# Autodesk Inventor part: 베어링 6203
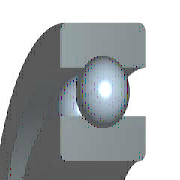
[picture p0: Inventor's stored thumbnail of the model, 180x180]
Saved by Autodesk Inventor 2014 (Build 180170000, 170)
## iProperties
IsCustomPart: 0
Company: 한국ATC센터
Created: 2014-10
Part Number: 베어링 6203
Material: Steel, Mild
Description: 깊은 그루브 볼 베어링
Document SubType Name: Modeling
Standard: KS B 2023
Designer: KYOUNG IL JANG
Standards Organization: KS
Language: ko-KR
Size Designation: 6203 - 17 x 40 x 12
Categories: <MemberInstance><Categories><Category DisplayName="샤프트 부품" InternalName="7f7aeb1f-a693-4053-b835-cee3144e0d98" Mnemonic="SHFT"><Category DisplayName="베어링" Inter
Density: 7.86 g/cm^3
Mass: 64.9809 g
Surface Area: 64.3582 cm^2
Volume: 8.26729 cm^3
Appearance: 강철 - 광택
Author: KYOUNG IL JANG
Revision Number: 1
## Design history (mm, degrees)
sketch "스케치" dims "d0" = 5.98 (= -0.26 x WD + 0.26 x BD)
  geometry: L1 (3.01, 14.25)-(8.99, 14.25); L2 (6, 14.25)-(6, 11.26); L3 (6, 14.25)-(6, 17.24); L4 (3.778, 12.249)-(0, 12.249); L5 (0, 8.5)-(12, 8.5); L6 (3.778, 16.251)-(0, 16.251); L7 (0, 20)-(12, 20); L8 (12, 8.5)-(12, 12.249); L9 (8.222, 12.249)-(12, 12.249); L10 (8.222, 16.251)-(12, 16.251); L11 (12, 20)-(12, 16.251); L12 (-1.4, 0)-(8.4, 0) reference; L13 (0, -0.3)-(0, 5.3) reference
  constraints: 22 end point, 4 point on line, 2 collinear, 2 perpendicular, 2 symmetric about line, 1 midpoint, 1 parallel, 14 other
  dimensions: "d9" = 17 diameter of L5 L12 (= WD); "d11" = 40 diameter of L7 L12 (= BD); "d12" = 12 distance between parallel lines of L8 L13 (= KB); "d13" = 24.498 diameter of L9 L12 (= 0.326 x BD + 0.674 x WD)
revolve "본체" stored, may be unused: angle "d6" = 90 deg
revolve "볼" stored, may be unused: angle "d7" = 90 deg
pattern_circular "IDS_ARRAYBALL[SIMPL:T]" dims angle "d3" = 360 deg
body "Solid1"
fillet "모깎기1" dims "d1" = 0.6 (= KRS)
other parameters: "WD" = 17 [user parameter; used in 5 equation terms], "BD" = 40 [user parameter; used in 5 equation terms], "KB" = 12 [user parameter; used in 1 equation term], "KRS" = 0.6 [user parameter; used in 1 equation term], "d4" = 0, "d5" = 0, "d8" = 0, "d14" = 0, "d15" = 0, "BBA" = 0 [user parameter], "BC0" = 4750000 [user parameter], "BC" = 9560000 [user parameter], "WR" = 8.5 (= 0.5 x WD) [user parameter]
